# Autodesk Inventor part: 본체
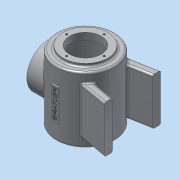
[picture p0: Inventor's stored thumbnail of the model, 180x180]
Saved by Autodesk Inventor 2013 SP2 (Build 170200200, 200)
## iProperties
Created: 2015-01
Part Number: 본체
Material: 알루미늄 6061
Document SubType Name: Modeling
Designer: dgall
Density: 2.71 g/cm^3
Mass: 1021.94 g
Surface Area: 1062.48 cm^2
Volume: 377.099 cm^3
Author: dgall
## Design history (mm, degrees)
sketch "스케치1"
  geometry: C1 r 50 at (0, 0); 1 further point
  constraints: 1 centre point, 1 coincident
  dimensions: "d0" = 100 diameter of C1
extrude "돌출1" new body sketch "스케치1" distance "d2" = 112; taper "d3" = 0 deg
sketch "스케치2"
  geometry: C1 r 50 at (0, 0) reference; C2 r 38 at (0, 0)
  constraints: 1 centre point, 1 coincident
  dimensions: "d4" = 76 diameter of C2
extrude "돌출2" join sketch "스케치2" distance "d6" = 5; taper "d7" = 0 deg
node "작업 평면1"
node "작업 평면2"
sketch "스케치3"
  geometry: L1 (50, 0)-(50, -112) reference; L2 (38, -117)-(-38, -117) reference; C1 r 38 at (0, -55); 1 further point
  constraints: 1 centre point, 1 vertical alignment
  dimensions: "d9" = 76 diameter of C1; "d71" = 62 distance from line of L2 C1.centre
extrude "돌출3" join sketch "스케치3" stored distance "d11" = 10; taper "d12" = 0 deg
node "작업 평면3"
sketch "스케치4"
  geometry: L1 (-30.865, 39.336)-(-80, 48); L2 (-80, 48)-(-80, 34); L3 (-80, 34)-(-30.865, 25.336); L4 (62, 38)-(62, -38) reference; L5 (-30.865, 39.336)-(-30.865, 25.336); 2 further points
  constraints: 8 end point, 2 parallel, 1 vertical, 1 vertical alignment, 2 other
  dimensions: "d13" = 48 vertical distance of point (0, 0) L1.end; "d14" = 100 deg angle of L2 L1; "d15" = 142 distance between parallel lines of L2 L4; "d16" = 14 distance of L1.end L2.end
extrude "돌출4" join sketch "스케치4" stored distance "d17" = 80; taper "d18" = 0 deg
sketch "스케치6"
  geometry: C1 r 38 at (0, 0) reference; C2 r 27 at (0, 0)
  constraints: 1 centre point, 1 coincident
  dimensions: "d19" = 54 diameter of C2
extrude "돌출5" cut sketch "스케치6" distance "d21" = 13; taper "d22" = 0 deg
sketch "스케치7"
  geometry: C1 r 27 at (0, 0) reference; C2 r 45 at (0, 0)
  constraints: 1 centre point, 1 coincident
  dimensions: "d23" = 90 diameter of C2
extrude "돌출6" cut sketch "스케치7" distance "d25" = 97; taper "d26" = 0 deg
sketch "스케치8" dims "d27" = 64
  geometry: C1 r 27 at (0, 0) reference; C2 r 38 at (0, 0) reference; 2 further points
  constraints: 2 horizontal alignment, 1 coincident, 2 other
hole "구멍1" sketch "스케치8" at (32, 0) diameter "d29" = 3.242; stored, may be unused: countersink angle "d33" = 90 deg, drill point angle "d35" = 118 deg; dims "d30" = 8, "d31" = 4, "d32" = 2, "d34" = 10
sketch "스케치9"
  geometry: C1 r 38 at (0, 0) reference; C2 r 27 at (0, 0); 1 further point
  constraints: 1 centre point, 1 coincident
  dimensions: "d39" = 54 diameter of C2
extrude "돌출7" cut sketch "스케치9" stored distance "d41" = 97; taper "d42" = 0 deg
sketch "스케치10" dims "d43" = 64
  geometry: C1 r 27 at (0, 0) reference; C2 r 38 at (0, 0) reference; 3 further points
  constraints: 2 vertical alignment, 1 coincident, 2 other
hole "구멍2" sketch "스케치10" at (0, 32) diameter "d45" = 3.242; stored, may be unused: countersink angle "d49" = 90 deg, drill point angle "d51" = 118 deg; dims "d46" = 8, "d47" = 4, "d48" = 2, "d50" = 10
node "작업 평면4"
sketch "스케치11"
  geometry: L1 (-50, 0)-(-50, -112) reference; L2 (50, 0)-(50, -112) reference; L3 (-6, -83)-(6, -83); L4 (6, -83)-(6, -29); L5 (6, -29)-(-6, -29); L6 (-6, -29)-(-6, -83); L7 (-50, -112)-(50, -112) reference; L8 (-50, 0)-(50, 0) reference; 5 further points
  constraints: 8 end point, 4 midpoint, 2 parallel, 1 horizontal, 1 horizontal alignment, 1 perpendicular, 1 vertical alignment
  dimensions: "d56" = 54 distance of L5.end L3.start; "d58" = 12 distance of L3.start L3.end
extrude "돌출8" join sketch "스케치11" stored distance "d59" = 97; taper "d60" = 0 deg
sketch "스케치12"
  geometry: L1 (-6, -83)-(6, -83) reference; L2 (-50, 0)-(-50, -112) reference; L3 (-62, -93)-(-62, -17) reference; 4 further points
  constraints: 2 midpoint, 1 horizontal alignment, 1 vertical alignment, 1 other
feature "엠보싱1" sketch "스케치12" dims "d61" = 0.5, "d62" = 0
fillet "모깎기1" dims "d63" = 3
chamfer "모따기1" distance "d65" = 1; stored, may be unused: second distance "d66" = 2, angle "d67" = 45 deg
fillet "모깎기3" dims "d68" = 3
fillet "모깎기4" dims "d69" = 3
fillet "모깎기5" dims "d70" = 3
fillet "모깎기6" dims "d72" = 3
sketch "스케치14"
  geometry: C1 r 38 at (0, 0) reference; C2 r 27 at (0, 0)
  constraints: 1 centre point, 1 coincident
  dimensions: "d73" = 54 diameter of C2
extrude "돌출9" cut sketch "스케치14" distance "d75" = 12; taper "d76" = 0 deg
node "솔리드1"
mirror "대칭1"
mirror "대칭2"
pattern_circular "원형 패턴1" dims angle "d37" = 360 deg
mirror "대칭4"
pattern_circular "원형 패턴2" dims angle "d53" = 360 deg
other parameters: "d8" = -62, "d55" = -52
